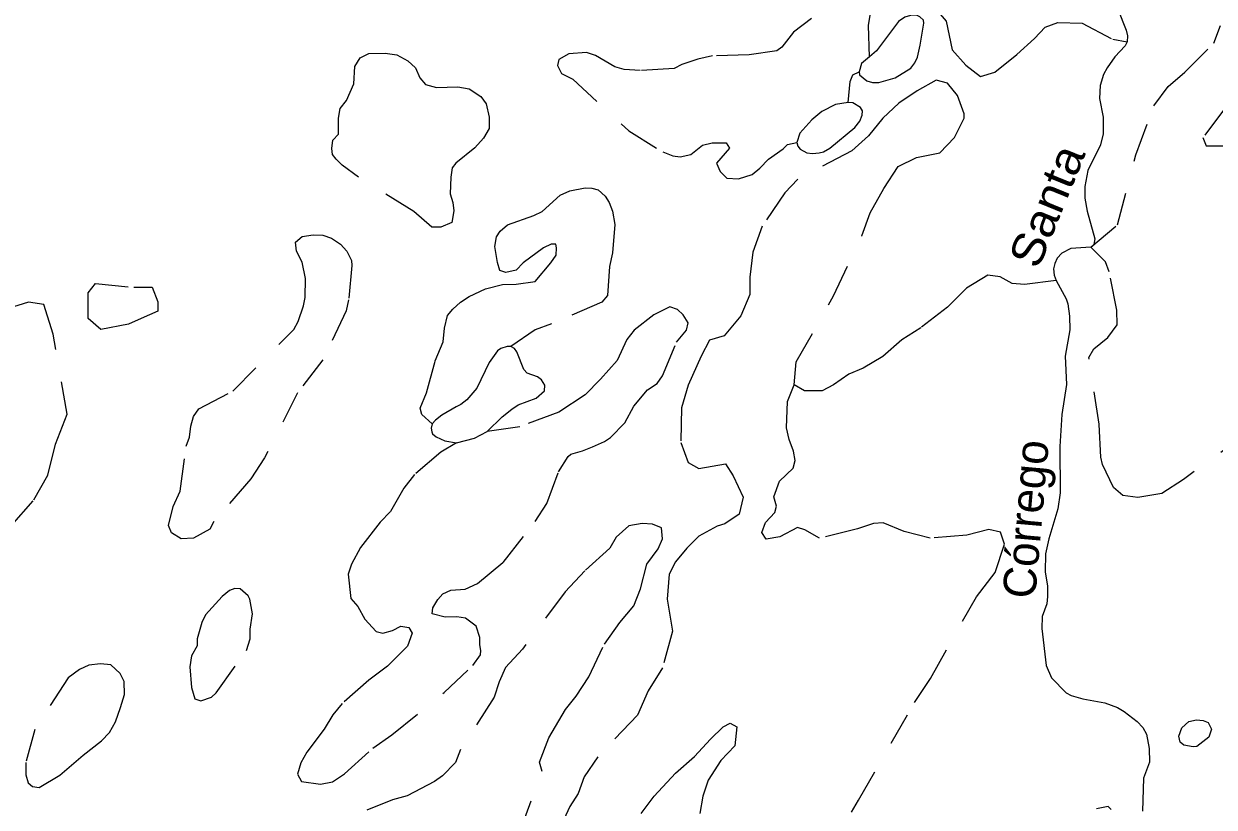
# Model space of a CAD drawing. Extents: x 344.9 to 371, y 7566.4 to 7594.3.
# Drawn here: x 363.484 to 367.111, y 7576.351 to 7578.737 of the extents above; entities that cross this region are included whole.
import ezdxf
from ezdxf.enums import TextEntityAlignment as Align

# ---------------------------------------------------------------- set-up
doc = ezdxf.new("R2010")
doc.units = 0
doc.header["$LTSCALE"] = 0.04
doc.linetypes.add('LONG_DASHED', pattern=[7.5, 6, -1.5])
doc.linetypes.add('SHORT_DASHED', pattern=[2.7, 1.5, -1.2])
for name, color, linetype, lineweight in [('17', 7, 'SHORT_DASHED', 13), ('2', 7, 'Continuous', 25), ('21', 7, 'SHORT_DASHED', 13), ('3', 7, 'LONG_DASHED', 25), ('7', 7, 'Continuous', 25)]:
    doc.layers.add(name, color=color, linetype=linetype, lineweight=lineweight)
doc.layers.add('61', color=7, linetype='Continuous')

msp = doc.modelspace()

# ---------------------------------------------------------------- linework, layer by layer
at = {"layer": '17'}
for points in [[(367.2121, 7577.4906), (367.0173, 7577.349), (366.951, 7577.3068), (366.8787, 7577.2947), (366.8325, 7577.3008), (366.8043, 7577.3249), (366.7702, 7577.3952), (366.7652, 7577.4169), (366.7603, 7577.5176), (366.7288, 7577.7211), (366.7442, 7577.7469), (366.7865, 7577.7819), (366.8154, 7577.8201), (366.8144, 7577.8644), (366.7906, 7577.982), (366.7793, 7578.0124), (366.7347, 7578.0566)], [(366.0055, 7576.3364), (366.0273, 7576.3724), (366.198, 7576.6705), (366.2465, 7576.7433), (366.3863, 7576.9923), (366.4432, 7577.0656), (366.4717, 7577.1518), (366.46, 7577.1887), (366.424, 7577.197), (366.357, 7577.1794), (366.2457, 7577.1708), (366.1662, 7577.1908), (366.1026, 7577.2168), (366.0733, 7577.2155), (366.0239, 7577.1988), (365.9084, 7577.1703), (365.864, 7577.1955), (365.8414, 7577.203), (365.7878, 7577.1746), (365.7459, 7577.1679), (365.7325, 7577.188), (365.7443, 7577.2181), (365.7727, 7577.2482), (365.7777, 7577.2683), (365.7694, 7577.2968), (365.7861, 7577.3436), (365.828, 7577.3838), (365.8347, 7577.4072), (365.8296, 7577.4357), (365.8163, 7577.4709), (365.8079, 7577.506), (365.8112, 7577.5864), (365.8308, 7577.6376)]]:
    msp.add_lwpolyline(points, dxfattribs=at)
at = {"layer": '2'}
msp.add_lwpolyline([(367.0185, 7576.5401), (367.0077, 7576.5488), (367.003, 7576.567), (367.0125, 7576.5933), (367.0333, 7576.612), (367.057, 7576.6173), (367.0769, 7576.6155), (367.0924, 7576.6093), (367.1024, 7576.5891), (367.095, 7576.5649), (367.0581, 7576.5361), (367.0467, 7576.5345)], close=True, dxfattribs=at)
at = {"layer": '21'}
for points in [[(366.445, 7579.1322), (366.3778, 7579.0673), (366.3338, 7579.0117), (366.2782, 7578.9237), (366.2527, 7578.8751), (366.2296, 7578.8427), (366.225, 7578.8126), (366.2643, 7578.7802), (366.2944, 7578.7454), (366.313, 7578.6574), (366.3546, 7578.6111), (366.3987, 7578.5764), (366.4429, 7578.5893), (366.5098, 7578.6435), (366.5631, 7578.6922), (366.5955, 7578.7269), (366.6349, 7578.7408), (366.709, 7578.7385), (366.8016, 7578.6898), (366.8458, 7578.6816)], [(366.0612, 7578.6367), (366.0573, 7578.7315), (366.0643, 7578.7693)], [(365.8841, 7578.7531), (365.8292, 7578.7111), (365.7935, 7578.6662), (365.7789, 7578.6543), (365.6942, 7578.6426), (365.5826, 7578.6389), (365.5378, 7578.6289), (365.4893, 7578.6133), (365.4655, 7578.6005), (365.3621, 7578.5946), (365.3137, 7578.5982), (365.2844, 7578.6055), (365.2258, 7578.6407), (365.1983, 7578.649), (365.1444, 7578.6453), (365.1142, 7578.6279), (365.1105, 7578.6096), (365.1224, 7578.5859), (365.1572, 7578.5685), (365.3273, 7578.4107), (365.4307, 7578.3466), (365.4618, 7578.3348), (365.4838, 7578.3315), (365.5167, 7578.3388), (365.5524, 7578.3672), (365.5817, 7578.3745), (365.6237, 7578.3745), (365.6338, 7578.3581), (365.5945, 7578.3123), (365.6054, 7578.2876), (365.6256, 7578.2666), (365.6613, 7578.2648), (365.7033, 7578.2776), (365.7271, 7578.2968), (365.7527, 7578.3247), (365.7975, 7578.3558), (365.8113, 7578.3695), (365.8393, 7578.3751)], [(366.7347, 7578.0566), (366.8165, 7578.1248), (366.8719, 7578.3378), (366.9272, 7578.4871), (366.9708, 7578.5458), (367.0211, 7578.5894), (367.1101, 7578.6783), (367.1302, 7578.732)], [(365.9961, 7578.4976), (366.0022, 7578.5613), (366.0102, 7578.5812), (366.0293, 7578.5907)], [(365.8308, 7577.6376), (365.8377, 7577.7071), (365.9512, 7577.9086), (366.0369, 7578.0915), (366.0624, 7578.161), (366.1041, 7578.2351), (366.1481, 7578.3023), (366.2036, 7578.3301), (366.2754, 7578.344), (366.3194, 7578.3903), (366.3495, 7578.4494), (366.3495, 7578.4632), (366.3287, 7578.5188), (366.2986, 7578.5559), (366.2638, 7578.5651), (366.2059, 7578.5327), (366.1503, 7578.4957), (366.1017, 7578.4494), (366.0577, 7578.3961), (366.0067, 7578.3498), (365.8423, 7578.2641), (365.8029, 7578.2224), (365.7334, 7578.1205), (365.7056, 7578.0418), (365.6963, 7577.9653), (365.6963, 7577.9121), (365.6685, 7577.8472), (365.6176, 7577.787), (365.5736, 7577.7731), (365.5481, 7577.7245), (365.5087, 7577.6365), (365.4879, 7577.567), (365.4856, 7577.4617), (365.5088, 7577.4014), (365.5412, 7577.3829), (365.6222, 7577.3968), (365.6454, 7577.3598), (365.6755, 7577.2949), (365.6639, 7577.244), (365.6199, 7577.2139), (365.5968, 7577.2069), (365.5412, 7577.1768), (365.5041, 7577.1398), (365.4694, 7577.0981), (365.4509, 7577.061), (365.4439, 7576.9846), (365.4601, 7576.8874), (365.43, 7576.7751), (365.386, 7576.7056), (365.3536, 7576.6315), (365.2331, 7576.5041), (365.1914, 7576.4439), (365.1729, 7576.393), (365.1474, 7576.3536), (365.1127, 7576.276)], [(367.1679, 7578.5688), (367.1958, 7578.545), (367.184, 7578.5131), (367.1421, 7578.4779), (367.0767, 7578.3906), (367.0867, 7578.3655), (367.1426, 7578.3657)], [(364.7285, 7577.5182), (364.6965, 7577.5468), (364.6916, 7577.5665), (364.7113, 7577.6133), (364.7372, 7577.7107), (364.7619, 7577.7681), (364.7656, 7577.81), (364.7754, 7577.8483), (364.7915, 7577.868), (364.8149, 7577.8889), (364.8408, 7577.9062), (364.8913, 7577.9296), (364.9431, 7577.9432), (364.9838, 7577.9444), (365.0418, 7577.9518), (365.0899, 7578.0091), (365.1059, 7578.0326), (365.1072, 7578.0547), (365.1047, 7578.0658), (365.0911, 7578.0658), (365.0677, 7578.0547), (365.006, 7578.0091), (364.9838, 7577.9869), (364.953, 7577.9795), (364.9345, 7577.9857), (364.9271, 7578.0104), (364.9197, 7578.0584), (364.9247, 7578.088), (364.9358, 7578.1053), (364.9579, 7578.125), (365.0381, 7578.1534), (365.064, 7578.1657), (365.1183, 7578.215), (365.1478, 7578.2286), (365.1947, 7578.2372), (365.2144, 7578.2366), (365.2342, 7578.2317), (365.2551, 7578.2119), (365.2675, 7578.1922), (365.2773, 7578.1663), (365.2847, 7578.1256), (365.2773, 7578.0393), (365.2687, 7577.9974), (365.2625, 7577.9099), (365.2452, 7577.8896), (365.0923, 7577.823), (365.0418, 7577.8045), (364.9682, 7577.7545)], [(366.6291, 7577.955), (366.5325, 7577.9433), (366.4955, 7577.9456), (366.4584, 7577.9665), (366.4213, 7577.9711), (366.3565, 7577.9317), (366.2986, 7577.8738), (366.2175, 7577.8113), (366.1596, 7577.7742), (366.1017, 7577.7233), (366.0415, 7577.6886), (365.9975, 7577.67), (365.9512, 7577.6376), (365.9165, 7577.6191), (365.8632, 7577.6191), (365.8308, 7577.6376)], [(363.4464, 7577.2089), (363.5148, 7577.2867), (363.5572, 7577.3622), (363.5808, 7577.4565), (363.6162, 7577.5484), (363.5737, 7577.7913), (363.5454, 7577.8821), (363.4982, 7577.8892), (363.4369, 7577.8703)], [(364.8025, 7577.4603), (364.7545, 7577.4324), (364.6745, 7577.3642), (364.6425, 7577.3223), (364.6018, 7577.252), (364.5697, 7577.2187), (364.5105, 7577.1423), (364.4822, 7577.0917), (364.4723, 7577.0609), (364.4809, 7576.9869), (364.5019, 7576.9622), (364.5229, 7576.924), (364.5574, 7576.8858), (364.5784, 7576.8815), (364.608, 7576.8889), (364.6326, 7576.9024), (364.6573, 7576.8987), (364.6671, 7576.8815), (364.6536, 7576.842), (364.5919, 7576.7804), (364.5352, 7576.7385), (364.4538, 7576.667), (364.4255, 7576.6324), (364.3996, 7576.5893), (364.3466, 7576.5184), (364.3281, 7576.4864), (364.3182, 7576.4518), (364.3305, 7576.4296), (364.3885, 7576.421), (364.4243, 7576.4284), (364.4613, 7576.4531), (364.5476, 7576.5307), (364.6055, 7576.5714), (364.7646, 7576.7002), (364.8521, 7576.7828), (364.8756, 7576.8149), (364.8768, 7576.8285), (364.8731, 7576.8457), (364.8731, 7576.8679), (364.862, 7576.9024), (364.8299, 7576.9271), (364.804, 7576.9308), (364.7682, 7576.9302), (364.7288, 7576.94), (364.73, 7576.9585), (364.746, 7576.9832), (364.7608, 7577.0005), (364.7855, 7577.0116), (364.8287, 7577.0153), (364.8669, 7577.0325), (364.9446, 7577.0966), (365.042, 7577.2212), (365.0778, 7577.2761), (365.1135, 7577.3722), (365.1431, 7577.4191), (365.1505, 7577.4265), (365.1863, 7577.4363), (365.2171, 7577.4487), (365.2529, 7577.4647), (365.2714, 7577.477), (365.3157, 7577.5214), (365.3428, 7577.5726), (365.3848, 7577.6219), (365.4143, 7577.6416), (365.4304, 7577.665), (365.4723, 7577.7674), (365.5031, 7577.8044), (365.508, 7577.826), (365.4932, 7577.8506), (365.476, 7577.8667), (365.4525, 7577.8753), (365.4032, 7577.8506), (365.344, 7577.8038), (365.3218, 7577.7754), (365.2922, 7577.7113), (365.2417, 7577.6546), (365.1948, 7577.6065), (365.1146, 7577.5541)], [(365.1146, 7577.5541), (364.995, 7577.5097), (364.8963, 7577.4956)], [(364.9954, 7576.2766), (365.0633, 7576.4598), (365.0556, 7576.4886), (365.0838, 7576.5629), (365.135, 7576.6487), (365.167, 7576.6897), (365.2055, 7576.7486), (365.2529, 7576.8479), (365.3003, 7576.9132), (365.3425, 7576.9644), (365.363, 7577.0157), (365.3822, 7577.0912), (365.4168, 7577.1379), (365.4296, 7577.1687), (365.427, 7577.202), (365.4001, 7577.2135), (365.3681, 7577.2148), (365.3271, 7577.2084), (365.2887, 7577.1738), (365.2695, 7577.1405), (365.1939, 7577.0713), (365.1337, 7577.0073), (365.0031, 7576.8325), (364.9519, 7576.7762), (364.9327, 7576.7326), (364.9173, 7576.6865), (364.8149, 7576.5271), (364.7995, 7576.4874), (364.7598, 7576.4464), (364.7355, 7576.4297), (364.6522, 7576.3862), (364.6074, 7576.374), (364.5293, 7576.342)], [(365.3651, 7576.3316), (365.4045, 7576.3849), (365.4693, 7576.4543), (365.5272, 7576.5053), (365.5759, 7576.5585), (365.6152, 7576.5956), (365.6361, 7576.6072), (365.6569, 7576.5956), (365.65, 7576.5377), (365.6083, 7576.4937), (365.5689, 7576.4335), (365.5527, 7576.3849), (365.5434, 7576.3316)]]:
    msp.add_lwpolyline(points, dxfattribs=at)
for points in [[(364.4678, 7578.5032), (364.49, 7578.554), (364.4931, 7578.6071), (364.5087, 7578.6336), (364.5352, 7578.646), (364.5851, 7578.6476), (364.621, 7578.6429), (364.6538, 7578.6242), (364.6772, 7578.6024), (364.6912, 7578.5727), (364.7084, 7578.5525), (364.7411, 7578.5431), (364.8066, 7578.5447), (364.8409, 7578.5384), (364.8768, 7578.515), (364.8924, 7578.4932), (364.9018, 7578.4526), (364.9018, 7578.4183), (364.8846, 7578.3887), (364.8581, 7578.3591), (364.8004, 7578.3123), (364.7895, 7578.2982), (364.7848, 7578.2702), (364.7832, 7578.2187), (364.791, 7578.1922), (364.7941, 7578.1672), (364.7879, 7578.1314), (364.7551, 7578.1173), (364.7271, 7578.1173), (364.6725, 7578.1657), (364.504, 7578.2702), (364.4543, 7578.3067), (364.4354, 7578.3248), (364.4245, 7578.3388), (364.4229, 7578.3575), (364.4261, 7578.3825), (364.4432, 7578.4012), (364.4432, 7578.4495), (364.4479, 7578.4792)], [(364.3183, 7577.6129), (364.2173, 7577.4147), (364.1764, 7577.3515), (364.0636, 7577.2213), (364.0512, 7577.1978), (364.0016, 7577.1705), (363.9632, 7577.168), (363.9347, 7577.1866), (363.9247, 7577.2089), (363.9396, 7577.2672), (363.9607, 7577.3131), (363.9793, 7577.4507), (363.9892, 7577.4779), (363.9929, 7577.5114), (364.0016, 7577.5411), (364.0177, 7577.5647), (364.1206, 7577.618), (364.3066, 7577.8058), (364.3202, 7577.8306), (364.3363, 7577.8777), (364.3413, 7577.9038), (364.3423, 7577.9615), (364.3324, 7578.0111), (364.315, 7578.0446), (364.3125, 7578.0718), (364.3324, 7578.0892), (364.3658, 7578.0941), (364.3956, 7578.0929), (364.4216, 7578.0842), (364.4489, 7578.0656), (364.4687, 7578.0446), (364.4824, 7578.016), (364.4839, 7578.001), (364.4737, 7577.8958), (364.4663, 7577.8623), (364.3956, 7577.7136)], [(363.7191, 7577.8058), (363.6801, 7577.8394), (363.6801, 7577.8674), (363.6801, 7577.9178), (363.7024, 7577.9458), (363.8196, 7577.9346), (363.8755, 7577.9346), (363.8922, 7577.8898), (363.8922, 7577.8618), (363.842, 7577.8394), (363.8029, 7577.8226)], [(364.0888, 7576.9925), (364.0375, 7576.9374), (364.0262, 7576.9136), (364.0125, 7576.8636), (364.0125, 7576.8423), (363.9949, 7576.8123), (363.9899, 7576.7785), (363.9949, 7576.7159), (364.005, 7576.6809), (364.0237, 7576.6746), (364.0563, 7576.6859), (364.07, 7576.6996), (364.1626, 7576.8285), (364.1739, 7576.8636), (364.1739, 7576.8936), (364.1814, 7576.9399), (364.1726, 7576.9849), (364.1676, 7576.995), (364.1439, 7577.0162), (364.1276, 7577.0175), (364.1113, 7577.0112)], [(363.6189, 7576.7453), (363.5176, 7576.5875), (363.49, 7576.4876), (363.49, 7576.4495), (363.4979, 7576.4258), (363.5111, 7576.414), (363.5308, 7576.4114), (363.5939, 7576.4482), (363.6649, 7576.51), (363.7214, 7576.5533), (363.7451, 7576.5783), (363.7635, 7576.6112), (363.7793, 7576.6546), (363.7911, 7576.694), (363.7898, 7576.7335), (363.778, 7576.7584), (363.749, 7576.7847), (363.7175, 7576.7874), (363.682, 7576.7834), (363.6544, 7576.7703)]]:
    msp.add_lwpolyline(points, close=True, dxfattribs=at)
at = {"layer": '3'}
msp.add_line((366.0819, 7578.6546), (366.0612, 7578.6367), dxfattribs=at)
for points in [[(366.0293, 7578.5907), (366.0303, 7578.5814), (366.0524, 7578.5632), (366.0695, 7578.5581), (366.0893, 7578.5581), (366.1391, 7578.5726), (366.1862, 7578.6017), (366.1987, 7578.6183), (366.2069, 7578.6356), (366.2148, 7578.6714), (366.2267, 7578.7391), (366.2249, 7578.7478), (366.2143, 7578.7585), (366.2037, 7578.7631), (366.1861, 7578.7621), (366.1686, 7578.7573), (366.1493, 7578.7444), (366.0819, 7578.6546)], [(366.0612, 7578.6367), (366.0367, 7578.6156), (366.0293, 7578.5907)], [(365.8393, 7578.3751), (365.8425, 7578.3645), (365.8499, 7578.3555), (365.8702, 7578.344), (365.8868, 7578.3417), (365.9075, 7578.344), (365.9209, 7578.347), (365.9398, 7578.3581), (366.0159, 7578.421), (366.0311, 7578.4402), (366.0389, 7578.4591), (366.0394, 7578.472), (366.0329, 7578.4817), (366.0104, 7578.4958), (365.9961, 7578.4976)], [(365.9961, 7578.4976), (365.9573, 7578.4914), (365.9153, 7578.4702), (365.8849, 7578.4446)], [(365.8849, 7578.4446), (365.8485, 7578.4042), (365.8393, 7578.3751)], [(364.9682, 7577.7545), (364.9571, 7577.7545), (364.9372, 7577.7481), (364.9271, 7577.7411), (364.9016, 7577.7054), (364.8649, 7577.6276), (364.8335, 7577.5915), (364.8161, 7577.5771), (364.8012, 7577.5701)], [(364.8963, 7577.4956), (364.9416, 7577.54), (364.9708, 7577.5637), (364.9907, 7577.5762), (365.0457, 7577.5966), (365.0706, 7577.6188), (365.072, 7577.6364), (365.0613, 7577.6522), (365.0488, 7577.6614), (365.0183, 7577.673), (365.0077, 7577.6837), (364.9868, 7577.7379), (364.9789, 7577.7481), (364.9682, 7577.7545)], [(364.8012, 7577.5701), (364.7581, 7577.5446), (364.7382, 7577.5298), (364.7285, 7577.5182)], [(364.7285, 7577.5182), (364.7257, 7577.5053), (364.7271, 7577.4946), (364.7298, 7577.4881), (364.7409, 7577.4793), (364.7673, 7577.4668), (364.8025, 7577.4603)], [(364.8025, 7577.4603), (364.8575, 7577.4752), (364.8963, 7577.4956)]]:
    msp.add_lwpolyline(points, dxfattribs=at)
at = {"layer": '7'}
for points in [[(366.8172, 7578.7813), (366.843, 7578.7176), (366.8467, 7578.7006), (366.8458, 7578.6816)], [(366.8458, 7578.6816), (366.8398, 7578.6703), (366.808, 7578.6366), (366.7845, 7578.6031), (366.7739, 7578.5824), (366.7638, 7578.5489), (366.7614, 7578.5095), (366.7725, 7578.4524), (366.773, 7578.4019), (366.7642, 7578.3682), (366.7263, 7578.2897), (366.7171, 7578.2419), (366.7167, 7578.2059), (366.7241, 7578.166), (366.7471, 7578.082), (366.7439, 7578.0649), (366.7347, 7578.0566)], [(366.7347, 7578.0566), (366.6738, 7578.0529), (366.6466, 7578.0384), (366.6327, 7578.0231), (366.6249, 7578.0065), (366.6217, 7577.991), (366.6231, 7577.9712), (366.6291, 7577.955)], [(366.6291, 7577.955), (366.6595, 7577.8994), (366.6646, 7577.8839), (366.6701, 7577.8461), (366.671, 7577.8053), (366.6567, 7577.7245), (366.6613, 7577.6388), (366.6465, 7577.5469), (366.6405, 7577.45), (366.6413, 7577.3082), (366.6344, 7577.2595), (366.6072, 7577.1685), (366.5971, 7577.123), (366.5962, 7577.0678), (366.6027, 7577.0242), (366.6032, 7576.9926), (366.6009, 7576.9709), (366.5871, 7576.9314)], [(366.5871, 7576.9314), (366.5861, 7576.8956), (366.5991, 7576.7825), (366.6148, 7576.7449), (366.6595, 7576.6998), (366.6752, 7576.6915), (366.7107, 7576.6814), (366.7781, 7576.6687), (366.8164, 7576.6546), (366.8362, 7576.6431), (366.8763, 7576.6119), (366.8934, 7576.5935), (366.9049, 7576.5731), (366.9132, 7576.5304), (366.9141, 7576.4879), (366.8952, 7576.4399), (366.8929, 7576.3388)], [(366.7969, 7576.3445), (366.7876, 7576.3533), (366.7521, 7576.3459)]]:
    msp.add_lwpolyline(points, dxfattribs=at)

# ---------------------------------------------------------------- texts
at = {"layer": '61', "width": 1.1}
msp.add_text('Santa', height=0.1, rotation=67.817, dxfattribs=at).set_placement((366.6473, 7578.1639), align=Align.CENTER)
at = {"layer": '61'}
msp.add_text('Córrego', height=0.1, rotation=84.977, dxfattribs=at).set_placement((366.5863, 7577.2243), align=Align.CENTER)

doc.saveas('drawing.dxf')
